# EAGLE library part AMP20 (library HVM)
AMP MICROMATCH FEMALE HEADER.
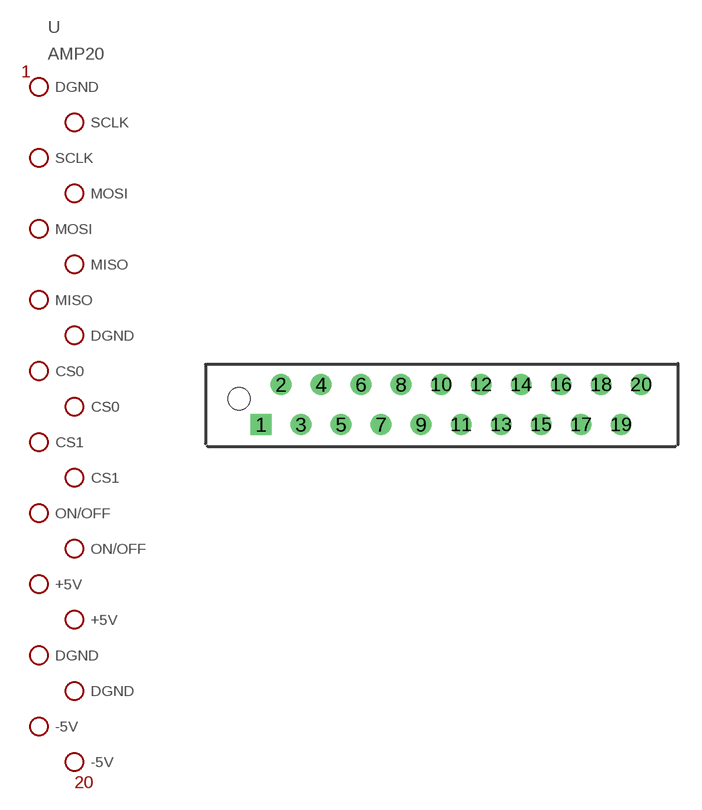
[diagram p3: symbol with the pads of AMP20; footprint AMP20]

Designator prefix U

## AMP20  [AMP20]
1  DGND  pas
2  SCLK  pas
3  SCLK  pas
4  MOSI  pas
5  MOSI  pas
6  MISO  pas
7  MISO  pas
8  DGND  pas
9  CS0  pas
10  CS0  pas
11  CS1  pas
12  CS1  pas
13  ON/OFF  pas
14  ON/OFF  pas
15  +5V  pas
16  +5V  pas
17  DGND  pas
18  DGND  pas
19  -5V  pas
20  -5V  pas

## Footprint AMP20 (pad centres in mm)
NEEDS TO BE CHECKED AGAINST AMP DATASHEET.
drill 0.813 square: 1 -12.7,-2.54
drill 0.813 round: 2 -11.43,0; 3 -10.16,-2.54; 4 -8.89,0; 5 -7.62,-2.54; 6 -6.35,0; 7 -5.08,-2.54; 8 -3.81,0; 9 -2.54,-2.54; 10 -1.27,0; 11 0,-2.54; 12 1.27,0; 13 2.54,-2.54; 14 3.81,0; 15 5.08,-2.54; 16 6.35,0; 17 7.62,-2.54; 18 8.89,0; 19 10.16,-2.54; 20 11.43,0
hole 1.422 at -14.1,-0.9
